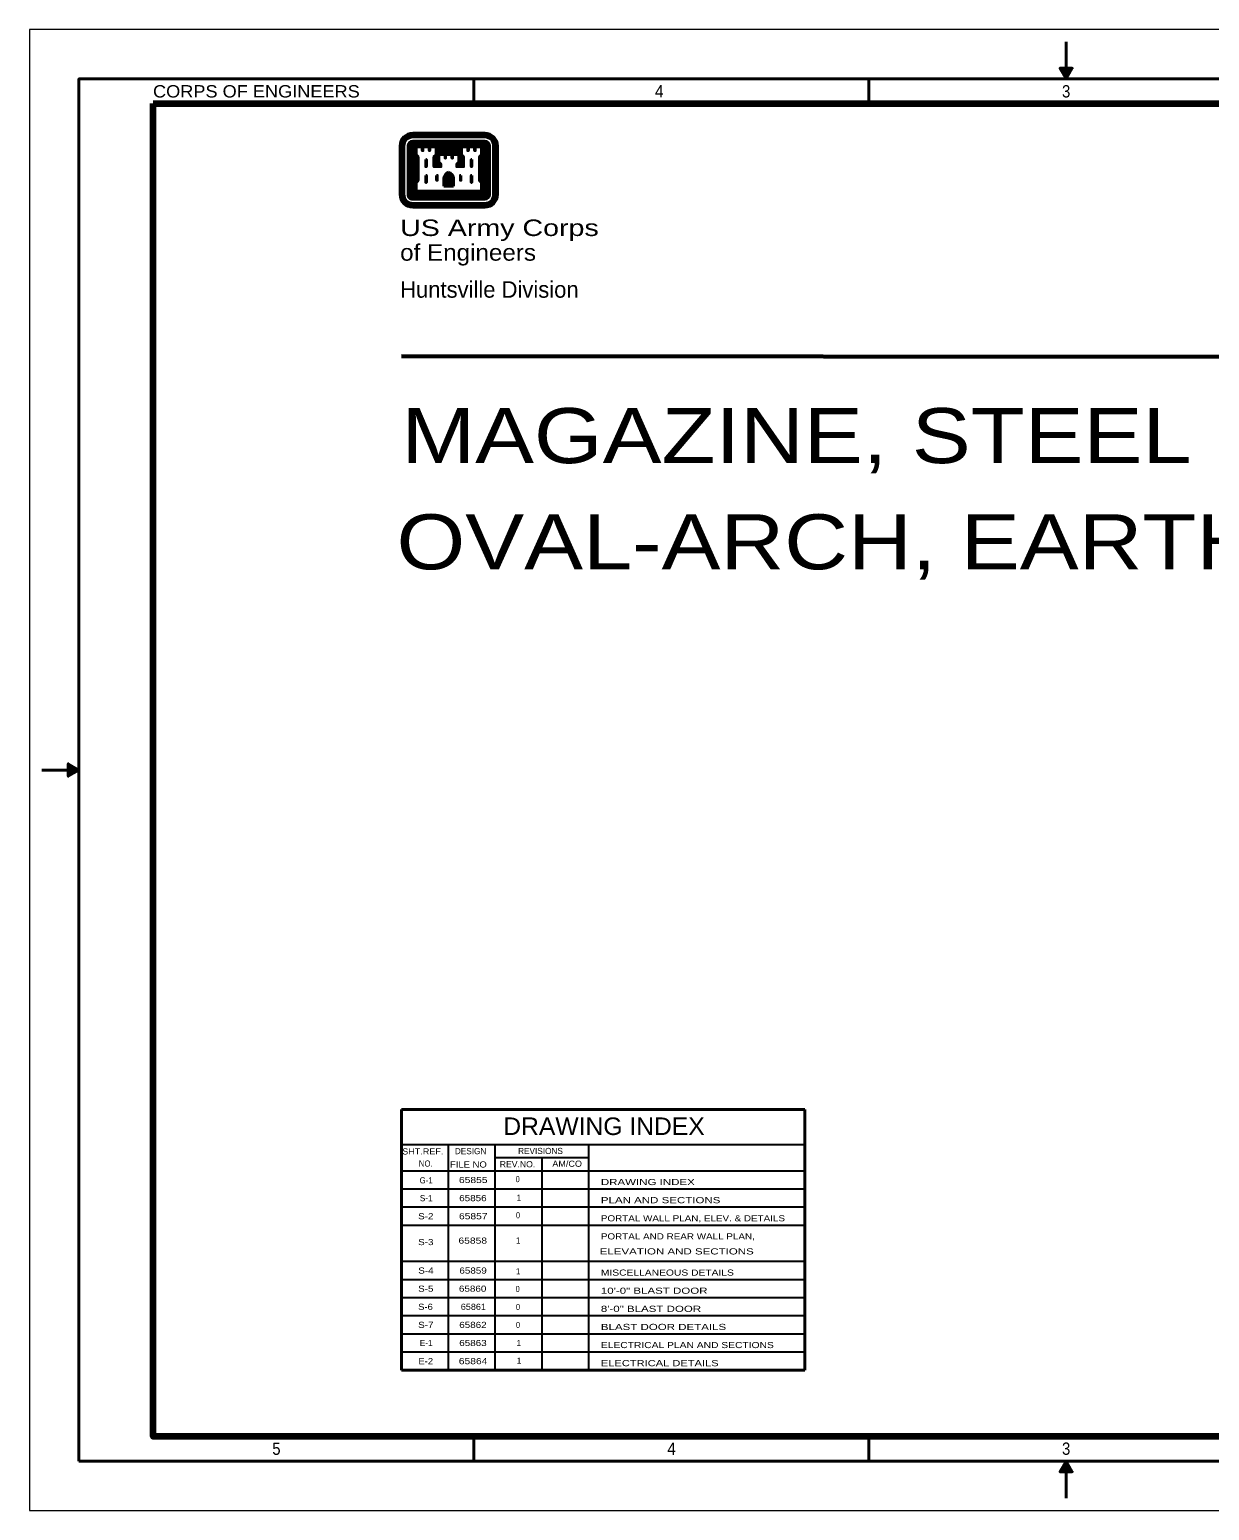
# Model space of a CAD drawing. Extents: x -7.4 to 34.6, y -51.3 to -21.3.
# Drawn here: x -7.35 to 16.55, y -51.27 to -21.27 of the extents above; entities that cross this region are included whole.
import ezdxf
from ezdxf.enums import TextEntityAlignment as Align

# ---------------------------------------------------------------- set-up
doc = ezdxf.new("R2010")
doc.units = 0
doc.header["$LTSCALE"] = 0.05
doc.layers.add('1', color=7, linetype='Continuous')
doc.layers.add('4', color=7, linetype='Continuous', lineweight=40)

msp = doc.modelspace()

# ---------------------------------------------------------------- linework, layer by layer
at = {"layer": '4', "lineweight": 13}
for p, q in [((-7.35198, -21.26987), (-7.35198, -51.26991)), ((34.64802, -21.26987), (-7.35198, -21.26987))]:
    msp.add_line(p, q, dxfattribs=at)
at = {"layer": '4'}
for p, q in [((13.64809, -21.51998), (13.64809, -22.26998)), ((1.64815, -22.26998), (1.64815, -22.76998)), ((9.64809, -22.26998), (9.64809, -22.76998)), ((0.15462, -23.62503), (0.15462, -24.61077)), ((0.16952, -23.62503), (0.16952, -24.61077)), ((0.19032, -23.62503), (0.19032, -24.61077)), ((0.21112, -23.62503), (0.21112, -24.61077)), ((0.23202, -23.62503), (0.23202, -24.61077)), ((0.31532, -23.62503), (0.31532, -24.61077)), ((0.33613, -23.62503), (0.33613, -24.61077)), ((0.357, -23.62503), (0.357, -24.61077)), ((0.37782, -23.62503), (0.37782, -24.61077)), ((0.39863, -23.62503), (0.39863, -24.61077)), ((1.86887, -23.42448), (0.41177, -23.42448)), ((1.86887, -23.44527), (0.41177, -23.44527)), ((1.86887, -23.52866), (0.41177, -23.52866)), ((1.86887, -23.54945), (0.41177, -23.54945)), ((1.86887, -23.57027), (0.41177, -23.57027)), ((1.86887, -23.59116), (0.41177, -23.59116)), ((1.86887, -23.61195), (0.41177, -23.61195)), ((0.4195, -23.62503), (0.4195, -24.60303)), ((0.44032, -23.62503), (0.44032, -24.58222)), ((0.91652, -23.6304), (1.36416, -23.6304)), ((0.91652, -23.6512), (1.36416, -23.6512)), ((0.91652, -23.67207), (1.36416, -23.67207)), ((0.91652, -23.6929), (1.36416, -23.6929)), ((1.84032, -23.62503), (1.84032, -24.58222)), ((1.86115, -23.62503), (1.86115, -24.60303)), ((1.88202, -23.62503), (1.88202, -24.61077)), ((1.90282, -23.62503), (1.90282, -24.61077)), ((1.92365, -23.62503), (1.92365, -24.61077)), ((1.94452, -23.62503), (1.94452, -24.61077)), ((1.96532, -23.62503), (1.96532, -24.61077)), ((2.04862, -23.62503), (2.04862, -24.61077)), ((2.06952, -23.62503), (2.06952, -24.61077)), ((2.09032, -23.62503), (2.09032, -24.61077)), ((2.11112, -23.62503), (2.11112, -24.61077)), ((2.12603, -23.62503), (2.12603, -24.61077)), ((0.45702, -23.83602), (0.45702, -24.33827)), ((0.47782, -23.85657), (0.47782, -24.31495)), ((0.91652, -23.7137), (1.36416, -23.7137)), ((0.91652, -23.73457), (1.36416, -23.73457)), ((0.91652, -23.7554), (1.36416, -23.7554)), ((1.80282, -23.85657), (1.80282, -24.31495)), ((1.82362, -23.8364), (1.82362, -24.33495)), ((1.04332, -24.43991), (1.04332, -24.27866)), ((1.06416, -24.43991), (1.06416, -24.27866)), ((1.08495, -24.43991), (1.08495, -24.27866)), ((1.10582, -24.43991), (1.10582, -24.27866)), ((1.12666, -24.43991), (1.12666, -24.27866)), ((1.154, -24.43991), (1.154, -24.27866)), ((1.17482, -24.43991), (1.17482, -24.27866)), ((1.1957, -24.43991), (1.1957, -24.27866)), ((1.2165, -24.43991), (1.2165, -24.27866)), ((1.23732, -24.43991), (1.23732, -24.27866)), ((1.84032, -24.58222), (0.44032, -24.58222)), ((1.04332, -24.43991), (1.23732, -24.43991)), ((1.86887, -24.62385), (0.41177, -24.62385)), ((1.86887, -24.64472), (0.41177, -24.64472)), ((1.86887, -24.66553), (0.41177, -24.66553)), ((1.86887, -24.68635), (0.41177, -24.68635)), ((1.86887, -24.70722), (0.41177, -24.70722)), ((1.86887, -24.79053), (0.41177, -24.79053)), ((1.86887, -24.81132), (0.41177, -24.81132)), ((1.86887, -24.83222), (0.41177, -24.83222)), ((1.86887, -24.85303), (0.41177, -24.85303)), ((1.86887, -24.8679), (0.41177, -24.8679)), ((1.86115, -24.60303), (0.4195, -24.60303)), ((0.18009, -27.87243), (31.14682, -27.89909)), ((0.18009, -27.87965), (31.1468, -27.9063)), ((0.18007, -27.9003), (31.1468, -27.92698)), ((-6.3518, -36.26993), (-7.10183, -36.26993)), ((0.17942, -43.14532), (0.17942, -48.43215)), ((8.3544, -43.14532), (0.17942, -43.14532)), ((8.3544, -43.14532), (8.3544, -48.43215)), ((8.3544, -48.43212), (0.17942, -48.43212)), ((1.64815, -49.76987), (1.64815, -50.26987)), ((9.64809, -49.76987), (9.64809, -50.26987)), ((13.64809, -50.26987), (13.64809, -51.01987))]:
    msp.add_line(p, q, dxfattribs=at)
at = {"layer": '4', "lineweight": 35}
for p, q in [((1.86887, -23.3679), (0.41177, -23.3679)), ((1.86887, -23.38277), (0.41177, -23.38277)), ((1.86887, -23.40366), (0.41177, -23.40366))]:
    msp.add_line(p, q, dxfattribs=at)
at = {"layer": '4', "lineweight": 25}
for p, q in [((8.3544, -43.86185), (0.17942, -43.86185)), ((1.12709, -43.86185), (1.12709, -48.43215)), ((2.0748, -43.86185), (2.0748, -48.43215)), ((3.97017, -43.86185), (3.97017, -48.43215)), ((8.3544, -44.39575), (0.17942, -44.39575)), ((3.97017, -44.12882), (2.0748, -44.12882)), ((3.02245, -44.12882), (3.02245, -48.43215)), ((8.3544, -44.76268), (0.17942, -44.76268)), ((8.3544, -45.12962), (0.17942, -45.12962)), ((8.3544, -45.49657), (0.17942, -45.49657)), ((8.3544, -46.23043), (0.17942, -46.23043)), ((8.3544, -46.59737), (0.17942, -46.59737)), ((8.3544, -46.96432), (0.17942, -46.96432)), ((8.3544, -47.33128), (0.17942, -47.33128)), ((8.3544, -47.69823), (0.17942, -47.69823)), ((8.3544, -48.06518), (0.17942, -48.06518)), ((8.3544, -48.06367), (2.47158, -48.06367))]:
    msp.add_line(p, q, dxfattribs=at)
at = {"layer": '4', "lineweight": 13}
msp.add_lwpolyline([(-7.35198, -51.26991), (34.64802, -51.26991), (34.64802, -21.26987)], dxfattribs=at)
at = {"layer": '4'}
for points in [[(13.64809, -22.26998), (13.77309, -22.0535), (13.52309, -22.0535)], [(-6.3518, -50.26987), (-6.3518, -22.26998), (33.64802, -22.26998), (33.64802, -50.26987)], [(0.45582, -23.62623), (0.45582, -23.8137), (0.49862, -23.85657), (0.49862, -24.31495), (0.45582, -24.35777), (0.45582, -24.56673), (1.82482, -24.56673), (1.82482, -24.35777), (1.78202, -24.31495), (1.78202, -23.85657), (1.82482, -23.8137), (1.82482, -23.62623), (1.64387, -23.62623), (1.50457, -23.62623), (1.3772, -23.62623), (1.3772, -23.8137), (1.42007, -23.85657), (1.42007, -24.02265), (1.32127, -24.02265), (1.32127, -24.00659), (1.36416, -23.9637), (1.36416, -23.7762), (1.1832, -23.7762), (1.0439, -23.7762), (0.91652, -23.7762), (0.91652, -23.9637), (0.9594, -24.00659), (0.9594, -24.02265), (0.86057, -24.02265), (0.86057, -23.85657), (0.90337, -23.8137), (0.90337, -23.62623), (0.72245, -23.62623), (0.5832, -23.62623)], [(0.47662, -23.64709), (0.47662, -23.8051), (0.5195, -23.84798), (0.5195, -24.3236), (0.47662, -24.3664), (0.47662, -24.5459), (1.804, -24.5459), (1.804, -24.3664), (1.76113, -24.3236), (1.76113, -23.84798), (1.804, -23.8051), (1.804, -23.64709), (1.67666, -23.64709), (1.67666, -23.72209), (1.6647, -23.72209), (1.6647, -23.64709), (1.53732, -23.64709), (1.53732, -23.72209), (1.52545, -23.72209), (1.52545, -23.64709), (1.39807, -23.64709), (1.39807, -23.8051), (1.44087, -23.84798), (1.44087, -24.04352), (1.30045, -24.04352), (1.30045, -23.99795), (1.34327, -23.95507), (1.34327, -23.79707), (1.21588, -23.79707), (1.21588, -23.87209), (1.20402, -23.87209), (1.20402, -23.79707), (1.07662, -23.79707), (1.07662, -23.87209), (1.0647, -23.87209), (1.0647, -23.79707), (0.93732, -23.79707), (0.93732, -23.95507), (0.9802, -23.99795), (0.9802, -24.04352), (0.8397, -24.04352), (0.8397, -23.84798), (0.88257, -23.8051), (0.88257, -23.64709), (0.7552, -23.64709), (0.7552, -23.72209), (0.74332, -23.72209), (0.74332, -23.64709), (0.6159, -23.64709), (0.6159, -23.72209), (0.604, -23.72209), (0.604, -23.64709)], [(0.67365, -23.90303), (0.67365, -24.04352), (0.68557, -24.04352), (0.68557, -23.90303)], [(1.60682, -23.90303), (1.60682, -24.04352), (1.5949, -24.04352), (1.5949, -23.90303)], [(0.67365, -24.22445), (0.67365, -24.36491), (0.68557, -24.36491), (0.68557, -24.22445)], [(0.89332, -24.22445), (0.89332, -24.32209), (0.9052, -24.32209), (0.9052, -24.22445)], [(1.38712, -24.22445), (1.38712, -24.32209), (1.37527, -24.32209), (1.37527, -24.22445)], [(1.60682, -24.22445), (1.60682, -24.36491), (1.5949, -24.36491), (1.5949, -24.22445)], [(-6.3518, -36.26993), (-6.56834, -36.39493), (-6.56834, -36.14493)], [(13.64809, -50.26987), (13.77309, -50.4864), (13.52309, -50.4864)]]:
    msp.add_lwpolyline(points, close=True, dxfattribs=at)
for points in [[(13.64868, -22.2273), (13.73702, -22.07432), (13.55918, -22.07432), (13.64707, -22.22655)], [(13.64745, -22.18777), (13.70093, -22.09518), (13.59527, -22.09518), (13.6493, -22.18878)], [(13.6478, -22.14548), (13.66485, -22.116), (13.63132, -22.116), (13.64645, -22.14215)], [(0.89416, -23.85248), (0.8814, -23.86522), (0.8814, -24.00182), (0.92512, -24.00182), (0.8957, -23.97235), (0.8957, -23.85145)], [(1.3865, -23.85248), (1.39925, -23.86522), (1.39925, -24.00182), (1.3555, -24.00182), (1.38495, -23.97235), (1.38495, -23.85145)], [(-6.39452, -36.27053), (-6.5475, -36.35882), (-6.5475, -36.181), (-6.39527, -36.26893)], [(-6.43402, -36.26928), (-6.52668, -36.32275), (-6.52668, -36.21709), (-6.43305, -36.27118)], [(-6.47635, -36.26968), (-6.50584, -36.28668), (-6.50584, -36.25318), (-6.47965, -36.2683)], [(13.64868, -50.31257), (13.73702, -50.46557), (13.55918, -50.46557), (13.64707, -50.31332)], [(13.64745, -50.35207), (13.70093, -50.44472), (13.59527, -50.44472), (13.6493, -50.3511)], [(13.6478, -50.39441), (13.66485, -50.4239), (13.63132, -50.4239), (13.64645, -50.3977)]]:
    msp.add_lwpolyline(points, dxfattribs=at)
at = {"layer": '4', "lineweight": 90}
msp.add_lwpolyline([(-4.85183, -22.76998), (33.14802, -22.76998), (33.14802, -49.76987), (-4.85183, -49.76987)], close=True, dxfattribs=at)
at = {"layer": '4'}
for centre, radius, start, end in [((0.41176, -23.62505), 0.25714, 89.99998, 179.99998), ((0.41176, -23.62505), 0.24226, 89.99998, 179.99998), ((1.86889, -23.62505), 0.25714, 359.99999, 89.99998), ((1.86889, -23.62505), 0.24226, 0.00002, 90.00001), ((0.41176, -23.62505), 0.22143, 89.99998, 179.99998), ((0.41176, -23.62505), 0.2006, 89.99998, 179.99998), ((0.41176, -23.62505), 0.17976, 89.99998, 179.99998), ((0.41176, -23.62505), 0.09643, 89.99998, 179.99998), ((0.41176, -23.62505), 0.07559, 89.99998, 179.99998), ((0.41176, -23.62505), 0.05476, 89.99998, 179.99998), ((0.41176, -23.62505), 0.03393, 89.99998, 179.99998), ((0.41176, -23.62505), 0.0131, 89.99998, 179.99998), ((1.86889, -23.62505), 0.22143, 0.00002, 90.00001), ((1.86889, -23.62505), 0.2006, 0.00002, 90.00001), ((1.86889, -23.62505), 0.17976, 0.00002, 90.00001), ((1.86889, -23.62505), 0.09643, 359.99999, 89.99998), ((1.86889, -23.62505), 0.07559, 359.99999, 89.99998), ((1.86889, -23.62505), 0.05476, 359.99999, 89.99998), ((1.86889, -23.62505), 0.03393, 359.99999, 89.99998), ((1.86889, -23.62505), 0.0131, 359.99999, 89.99998), ((1.17622, -24.28922), 0.13329, 105.66806, 176.05749), ((1.17622, -24.28922), 0.11245, 103.4698, 176.05749), ((1.17622, -24.28922), 0.09162, 103.4698, 176.05749), ((1.17622, -24.28922), 0.07079, 103.4698, 176.05749), ((1.10442, -24.28922), 0.04995, 3.94252, 76.53021), ((1.10442, -24.28922), 0.07079, 3.94252, 76.53021), ((1.10442, -24.28922), 0.09162, 3.94252, 76.53021), ((1.17622, -24.28922), 0.04995, 103.4698, 176.05749), ((1.10442, -24.28922), 0.11245, 3.94252, 76.53021), ((1.10442, -24.28922), 0.13329, 3.94252, 74.39486), ((0.41176, -24.61076), 0.25714, 180.00002, 270.00002), ((0.41176, -24.61076), 0.24226, 179.99998, 269.99998), ((0.41176, -24.61076), 0.22143, 179.99998, 269.99998), ((0.41176, -24.61076), 0.2006, 179.99998, 269.99998), ((0.41176, -24.61076), 0.17976, 179.99998, 269.99998), ((0.41176, -24.61076), 0.09643, 180.00002, 270.00002), ((0.41176, -24.61076), 0.07559, 180.00002, 270.00002), ((0.41176, -24.61076), 0.05476, 180.00002, 270.00002), ((0.41176, -24.61076), 0.03393, 180.00002, 270.00002), ((0.41176, -24.61076), 0.0131, 180.00002, 270.00002), ((1.86889, -24.61076), 0.25714, 270.00002, 0.00002), ((1.86889, -24.61076), 0.09643, 270.00002, 0.00002), ((1.86889, -24.61076), 0.07559, 270.00002, 0.00002), ((1.86889, -24.61076), 0.05476, 270.00002, 0.00002), ((1.86889, -24.61076), 0.03393, 270.00002, 0.00002), ((1.86889, -24.61076), 0.0131, 270.00002, 0.00002), ((1.86889, -24.61076), 0.17976, 270.00002, 0.00001), ((1.86889, -24.61076), 0.2006, 270.00002, 0.00001), ((1.86889, -24.61076), 0.22143, 270.00002, 0.00001), ((1.86889, -24.61076), 0.24226, 270.00002, 0.00001)]:
    msp.add_arc(centre, radius, start, end, dxfattribs=at)

# ---------------------------------------------------------------- texts
at = {"layer": '1', "width": 0.9}
for p in [(2.49435, -44.62007), (2.50087, -45.35241), (2.49435, -46.84636), (2.50086, -47.21091), (2.50086, -47.57544)]:
    msp.add_text('0', height=0.1245, dxfattribs=at).set_placement(p)
at = {"layer": '1'}
for p in [(2.51389, -44.99762), (2.50086, -45.86341), (2.50087, -46.48834), (2.51309, -47.94175), (2.51716, -48.30001)]:
    msp.add_text('1', height=0.1245, dxfattribs=at).set_placement(p)
at = {"layer": '4'}
for s, height, width, p in [('CORPS OF ENGINEERS', 0.25, 1.1, (-4.85183, -22.64498)), ('US Army Corps', 0.3333, 1.3, (0.15462, -25.4512)), ('of Engineers', 0.3333, 1.1, (0.15462, -25.95123)), ('MAGAZINE, STEEL   ', 1.115, 1.2, (0.18275, -30.05312)), ('OVAL-ARCH, EARTH COVERED   ', 1.115, 1.2, (0.08188, -32.2047)), ('DRAWING INDEX                   ', 0.1245, 1.4, (4.22157, -44.67982)), ('PLAN AND SECTIONS               ', 0.1245, 1.4, (4.22157, -45.04678)), ('PORTAL WALL PLAN, ELEV. & DETAILS', 0.1245, 1.2, (4.22157, -45.41373)), ('PORTAL AND REAR WALL PLAN,            ', 0.1245, 1.2, (4.22157, -45.78066)), ('ELEVATION AND SECTIONS          ', 0.1245, 1.4, (4.19793, -46.08505)), ('MISCELLANEOUS DETAILS    ', 0.1245, 1.25, (4.22157, -46.51452)), ('10\'-0" BLAST DOOR               ', 0.1245, 1.4, (4.22157, -46.88147)), ('8\'-0" BLAST DOOR                ', 0.1245, 1.4, (4.22157, -47.24843)), ('BLAST DOOR DETAILS        ', 0.1245, 1.4, (4.22157, -47.61538)), ('ELECTRICAL PLAN AND SECTIONS    ', 0.1245, 1.25, (4.22157, -47.98232)), ('ELECTRICAL DETAILS              ', 0.1245, 1.35, (4.22157, -48.34928))]:
    msp.add_text(s, height=height, dxfattribs=dict(at, width=width)).set_placement(p)
for s, height, width, p in [('4', 0.25, 0.95, (5.40435, -22.64498)), ('3', 0.25, 0.9, (13.64841, -22.64498)), ('DRAWING INDEX', 0.3559, 1.05, (4.28478, -43.66485)), ('SHT.REF.', 0.1246, 1.1, (0.61405, -44.05955)), ('NO.', 0.1245, 0.95, (0.67412, -44.30518)), ('FILE NO', 0.1246, 1.15, (1.53756, -44.32402)), ('REV.NO.', 0.1245, 1.05, (2.53273, -44.31847)), ('AM/CO', 0.1246, 1.1, (3.53848, -44.3089)), ('G-1', 0.1245, 0.95, (0.68199, -44.64553)), ('65855', 0.1245, 1.25, (1.63589, -44.63875)), ('65856', 0.1245, 1.2, (1.62952, -45.0057)), ('S-2', 0.1245, 1.2, (0.67457, -45.37265)), ('65857', 0.1245, 1.25, (1.63637, -45.37265)), ('S-3', 0.1245, 1.2, (0.67457, -45.89581)), ('65858', 0.1245, 1.25, (1.62613, -45.86651)), ('S-4', 0.1245, 1.2, (0.67752, -46.47345)), ('65859', 0.1245, 1.2, (1.63246, -46.47345)), ('S-5', 0.1245, 1.2, (0.67457, -46.8404)), ('65860', 0.1245, 1.2, (1.62414, -46.8404)), ('S-6', 0.1245, 1.15, (0.66821, -47.20735)), ('65861', 0.1245, 1.1, (1.63836, -47.20735)), ('S-7', 0.1245, 1.2, (0.67506, -47.5743)), ('65862', 0.1245, 1.2, (1.62997, -47.5743)), ('65863', 0.1245, 1.2, (1.62997, -47.94125)), ('E-2', 0.1245, 1.15, (0.67457, -48.3082)), ('65864', 0.1245, 1.25, (1.63295, -48.3082)), ('5', 0.25, 0.9, (-2.35154, -50.14487)), ('4', 0.25, 0.95, (5.65437, -50.14487)), ('3', 0.25, 0.9, (13.64841, -50.14487))]:
    msp.add_text(s, height=height, dxfattribs=dict(at, width=width)).set_placement(p, align=Align.CENTER)
msp.add_text('Huntsville Division', height=0.3333, dxfattribs=at).set_placement((0.15462, -26.7012))
for s, height, p in [('DESIGN', 0.1246, (1.58248, -44.05337)), ('REVISIONS', 0.1246, (2.99859, -44.05015)), ('S-1', 0.1245, (0.68293, -45.0057)), ('E-1', 0.1245, (0.68292, -47.94125))]:
    msp.add_text(s, height=height, dxfattribs=at).set_placement(p, align=Align.CENTER)

doc.saveas('drawing.dxf')
